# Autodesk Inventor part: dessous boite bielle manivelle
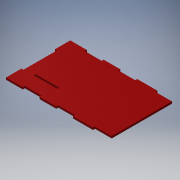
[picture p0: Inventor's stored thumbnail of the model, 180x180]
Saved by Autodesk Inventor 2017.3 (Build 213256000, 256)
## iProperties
Part Number: dessous boite bielle manivelle
Material: Générique
Document SubType Name: Modeling
Designer: ficho
Density: 1 g/cm^3
Appearance: Rouge
Author: ficho
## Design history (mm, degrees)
sketch "Esquisse1"
  geometry: L1 (18, 26.5)-(53, 26.5); L2 (53, 26.5)-(53, 23.5); L3 (53, 23.5)-(18, 23.5); L4 (18, 23.5)-(18, 26.5); L5 (50, 0)-(50, 3); L6 (50, 3)-(25, 3); L7 (25, 3)-(25, 0); L8 (100, 0)-(100, 3); L9 (100, 3)-(75, 3); L10 (75, 3)-(75, 0); L11 (50, 96)-(50, 93); L12 (50, 93)-(25, 93); L13 (25, 93)-(25, 96); L14 (100, 96)-(100, 93); L15 (100, 93)-(75, 93); L16 (75, 93)-(75, 96); L17 (25, 96)-(0, 96); L18 (130, 96)-(100, 96); L19 (75, 96)-(50, 96); L20 (0, 0)-(25, 0); L21 (0, 73)-(3, 73); L22 (3, 73)-(3, 23); L23 (3, 23)-(0, 23); L24 (50, 0)-(75, 0); L25 (100, 0)-(130, 0); L26 (0, 96)-(0, 73); L27 (0, 23)-(0, 0); L28 (130, 0)-(130, 3); L29 (130, 93)-(130, 96); L30 (130, 93)-(155, 93); L31 (155, 93)-(155, 3); L32 (155, 3)-(130, 3)
  constraints: 64 end point, 15 parallel, 5 horizontal, 5 perpendicular, 1 collinear, 1 point on line
  dimensions: "d2" = 35 distance of L2.end L3.end; "d5" = 3 distance between parallel lines of L3 L1; "d6" = 25 distance of L6.end L5.end; "d9" = 25 distance of L9.end L8.end; "d10" = 25 distance between parallel lines of L5 L10 (= d9); "d11" = 3 distance of L11.start L11.end; "d12" = 3 distance of L22.end L23.end; "d13" = 50 distance of L21.end L22.end; "d14" = 23 distance between parallel lines of L21 L17; "d15" = 23 distance between parallel lines of L23 L20; "d16" = 96 distance between parallel lines of L20 L17 (derived); "d17" = 96 distance between parallel lines of L24 L19; "d18" = 96 distance between parallel lines of L25 L18; "d22" = 25 distance of L28.end L31.end
extrude "Extrusion1" new body sketch "Esquisse1" distance "d20" = 3; taper "d21" = 0 deg
node "Solide1"
other parameters: "d0" = 96, "d3" = 18, "d4" = 23.5, "d7" = 3, "d8" = 25 (= d6)
